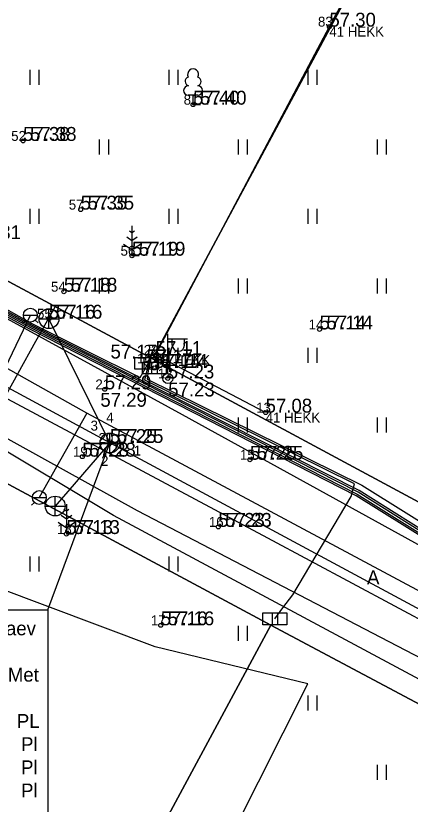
# Model space of a CAD drawing. Extents: x 640891 to 641083, y 6456526 to 6456669.
# Drawn here: x 640950.33 to 640970.21, y 6456556.9 to 6456596.6 of the extents above; entities that cross this region are included whole.
import ezdxf

# ---------------------------------------------------------------- set-up
doc = ezdxf.new("R2010")
doc.units = 0
for name, color, linetype in [('100koma2', 7, 'Continuous'), ('ABIJOONIS', 7, 'Continuous'), ('HALJASTUS', 7, 'Continuous'), ('KKAEV', 7, 'Continuous'), ('KORGUS', 7, 'Continuous'), ('KPKAABEL', 7, 'Continuous'), ('KTRASS', 7, 'Continuous'), ('MOOTKORG', 7, 'Continuous'), ('MOOTMPUNKT', 7, 'Continuous'), ('MOOTNR', 7, 'Continuous'), ('MOOTPIIR', 7, 'Continuous'), ('MPKAABEL', 7, 'Continuous'), ('PIIR', 7, 'Continuous'), ('POST', 7, 'Continuous'), ('PUU', 7, 'Continuous'), ('SITRASS', 7, 'Continuous'), ('SKTRASS', 7, 'Continuous'), ('TEE', 7, 'Continuous'), ('TORU_NR', 7, 'Continuous'), ('VKAEV', 7, 'Continuous'), ('VTRASS', 7, 'Continuous')]:
    doc.layers.add(name, color=color, linetype=linetype)

msp = doc.modelspace()

# ---------------------------------------------------------------- linework, layer by layer
at = {"layer": 'ABIJOONIS'}
msp.add_line((640951.949, 6456566.685), (640955.081, 6456575.091), dxfattribs=at)
msp.add_lwpolyline([(640942.489, 6456566.685), (640951.949, 6456566.685), (640951.949, 6456555.319), (640942.489, 6456555.319)], close=True, dxfattribs=at)
at = {"layer": 'HALJASTUS'}
for p, q in [((640951.045, 6456593.881), (640951.045, 6456593.119)), ((640951.5, 6456593.881), (640951.5, 6456593.119)), ((640958.045, 6456593.881), (640958.045, 6456593.119)), ((640958.5, 6456593.881), (640958.5, 6456593.119)), ((640965.045, 6456593.881), (640965.045, 6456593.119)), ((640965.5, 6456593.881), (640965.5, 6456593.119)), ((640954.545, 6456590.381), (640954.545, 6456589.619)), ((640955, 6456590.381), (640955, 6456589.619)), ((640961.545, 6456590.381), (640961.545, 6456589.619)), ((640962, 6456590.381), (640962, 6456589.619)), ((640968.545, 6456590.381), (640968.545, 6456589.619)), ((640969, 6456590.381), (640969, 6456589.619)), ((640951.045, 6456586.881), (640951.045, 6456586.119)), ((640951.5, 6456586.881), (640951.5, 6456586.119)), ((640958.045, 6456586.881), (640958.045, 6456586.119)), ((640958.5, 6456586.881), (640958.5, 6456586.119)), ((640965.045, 6456586.881), (640965.045, 6456586.119)), ((640965.5, 6456586.881), (640965.5, 6456586.119)), ((640954.545, 6456583.381), (640954.545, 6456582.619)), ((640955, 6456583.381), (640955, 6456582.619)), ((640961.545, 6456583.381), (640961.545, 6456582.619)), ((640962, 6456583.381), (640962, 6456582.619)), ((640968.545, 6456583.381), (640968.545, 6456582.619)), ((640969, 6456583.381), (640969, 6456582.619)), ((640958.045, 6456579.881), (640958.045, 6456579.119)), ((640958.5, 6456579.881), (640958.5, 6456579.119)), ((640965.045, 6456579.881), (640965.045, 6456579.119)), ((640965.5, 6456579.881), (640965.5, 6456579.119)), ((640961.545, 6456576.381), (640961.545, 6456575.619)), ((640962, 6456576.381), (640962, 6456575.619)), ((640968.545, 6456576.381), (640968.545, 6456575.619)), ((640969, 6456576.381), (640969, 6456575.619)), ((640951.045, 6456569.381), (640951.045, 6456568.619)), ((640951.5, 6456569.381), (640951.5, 6456568.619)), ((640958.045, 6456569.381), (640958.045, 6456568.619)), ((640958.5, 6456569.381), (640958.5, 6456568.619)), ((640961.545, 6456565.881), (640961.545, 6456565.119)), ((640962, 6456565.881), (640962, 6456565.119)), ((640965.045, 6456562.381), (640965.045, 6456561.619)), ((640965.5, 6456562.381), (640965.5, 6456561.619)), ((640968.545, 6456558.881), (640968.545, 6456558.119)), ((640969, 6456558.881), (640969, 6456558.119))]:
    msp.add_line(p, q, dxfattribs=at)
msp.add_lwpolyline([(640962.925, 6456576.62), (640957.383, 6456579.521), (640966.138, 6456596.056), (640972.417, 6456607.592), (640977.059, 6456616.501), (640985.041, 6456631.518)], dxfattribs=at)
at = {"layer": 'KKAEV'}
for p, q in [((640952.007, 6456580.849), (640952.007, 6456581.849)), ((640951.507, 6456581.349), (640952.507, 6456581.349)), ((640955.081, 6456574.591), (640955.081, 6456575.591)), ((640954.581, 6456575.091), (640955.581, 6456575.091)), ((640952.322, 6456571.413), (640952.322, 6456572.413)), ((640951.822, 6456571.913), (640952.822, 6456571.913))]:
    msp.add_line(p, q, dxfattribs=at)
for centre in [(640952.007, 6456581.349), (640955.081, 6456575.091), (640952.322, 6456571.913)]:
    msp.add_circle(centre, 0.5, dxfattribs=at)
at = {"layer": 'KORGUS'}
for centre in [(640959.27, 6456592.127), (640950.704, 6456590.303), (640953.606, 6456586.843), (640956.191, 6456584.52), (640952.76, 6456582.709), (640952.007, 6456581.349), (640965.643, 6456580.808), (640956.926, 6456579.098), (640957.317, 6456578.869), (640957.996, 6456578.338), (640954.822, 6456577.791), (640955.081, 6456575.091), (640953.689, 6456574.401), (640962.132, 6456574.246), (640960.539, 6456570.866), (640952.888, 6456570.505), (640957.641, 6456565.909)]:
    msp.add_circle(centre, 0.1, dxfattribs=at)
at = {"layer": 'KPKAABEL'}
msp.add_lwpolyline([(640977.507, 6456566.281), (640976.27, 6456566.95), (640967.49, 6456572.43), (640959.27, 6456576.625), (640951.05, 6456580.82), (640939.86, 6456586.9), (640935.075, 6456589.63), (640930.29, 6456592.36), (640924.23, 6456595.65), (640919.26, 6456598.135), (640914.117, 6456600.706)], dxfattribs=at)
at = {"layer": 'KTRASS'}
for points in [[(640955.081, 6456575.091), (640928.16, 6456589.63)], [(640955.081, 6456575.091), (640952.007, 6456581.349)], [(640955.081, 6456575.091), (640952.322, 6456571.913)], [(640976.059, 6456563.819), (640955.081, 6456575.091)]]:
    msp.add_lwpolyline(points, dxfattribs=at)
at = {"layer": 'MOOTMPUNKT'}
for centre in [(640966.138, 6456596.056), (640959.27, 6456592.127), (640950.704, 6456590.303), (640953.606, 6456586.843), (640956.191, 6456584.52), (640952.76, 6456582.709), (640952.007, 6456581.349), (640965.643, 6456580.808), (640957.383, 6456579.521), (640956.926, 6456579.098), (640957.317, 6456578.869), (640957.996, 6456578.338), (640954.822, 6456577.791), (640962.925, 6456576.62), (640955.081, 6456575.091), (640953.689, 6456574.401), (640962.132, 6456574.246), (640960.539, 6456570.866), (640952.888, 6456570.505), (640957.641, 6456565.909)]:
    msp.add_circle(centre, 0.1, dxfattribs=at)
at = {"layer": 'MOOTPIIR'}
msp.add_lwpolyline([(640976.662, 6456538.007), (640959.29, 6456546.142), (640961.328, 6456555.553), (640965.053, 6456562.959), (640957.364, 6456564.816), (640935.712, 6456572.952), (640933.007, 6456573.069), (640928.881, 6456566.092), (640925.582, 6456561.827), (640921.958, 6456562.765), (640911.417, 6456572.885), (640912.029, 6456574.013), (640921.076, 6456588.216), (640912.945, 6456593.7), (640910.627, 6456595.318), (640915.929, 6456603.505), (640924.706, 6456598.502), (640938.233, 6456631.58)], dxfattribs=at)
at = {"layer": 'MPKAABEL'}
for points in [[(640914.394, 6456601.133), (640919.49, 6456598.58), (640924.46, 6456596.09), (640927.495, 6456594.445), (640930.53, 6456592.8), (640935.32, 6456590.07), (640940.11, 6456587.34), (640945.625, 6456584.22), (640951.14, 6456581.1), (640953.87, 6456579.745), (640956.6, 6456578.39), (640957.06, 6456579.17)], [(640914.173, 6456600.793), (640919.31, 6456598.225), (640924.28, 6456595.74), (640927.31, 6456594.095), (640930.34, 6456592.45), (640935.125, 6456589.72), (640939.91, 6456586.99), (640945.495, 6456583.945), (640951.08, 6456580.9), (640959.31, 6456576.71), (640967.54, 6456572.52), (640971.93, 6456569.78), (640976.32, 6456567.04), (640977.56, 6456566.369)], [(640977.608, 6456566.451), (640976.37, 6456567.12), (640971.98, 6456569.865), (640967.59, 6456572.61), (640959.355, 6456576.785), (640951.12, 6456580.96), (640945.54, 6456584.015), (640939.96, 6456587.07), (640935.175, 6456589.8), (640930.39, 6456592.53), (640927.355, 6456594.18), (640924.32, 6456595.83), (640919.35, 6456598.315), (640914.227, 6456600.876)], [(640977.66, 6456566.54), (640976.42, 6456567.21), (640972.03, 6456569.95), (640967.64, 6456572.69), (640959.395, 6456576.855), (640951.15, 6456581.02), (640945.58, 6456584.09), (640940.01, 6456587.16), (640935.225, 6456589.89), (640930.44, 6456592.62), (640927.405, 6456594.27), (640924.37, 6456595.92), (640919.4, 6456598.405), (640914.283, 6456600.963)], [(640963.39, 6456566.23), (640963.8, 6456566.79), (640964.29, 6456567.45), (640967.23, 6456572.39), (640967.4, 6456573.03), (640956.84, 6456578.26), (640957.06, 6456579.17)], [(640957.06, 6456579.17), (640956.96, 6456578.31), (640962.37, 6456575.635), (640967.78, 6456572.96), (640976.57, 6456567.48), (640977.808, 6456566.792)]]:
    msp.add_lwpolyline(points, dxfattribs=at)
at = {"layer": 'PIIR'}
for points in [[(640957.22, 6456579.32), (640930.79, 6456593.51), (640960.76, 6456649.34), (640985.89, 6456632.73)], [(640983.63, 6456565.13), (640957.22, 6456579.32), (640985.89, 6456632.73), (641000.58, 6456623), (641011.01, 6456616.1)]]:
    msp.add_lwpolyline(points, close=True, dxfattribs=at)
for points in [[(640890.598, 6456615.08), (640904.36, 6456607.7), (640930.79, 6456593.51), (640957.22, 6456579.32), (640983.63, 6456565.13), (641002.905, 6456555.058)], [(640993.023, 6456550.09), (640989.66, 6456551.83), (640963.18, 6456565.91), (640936.74, 6456580.1), (640910.31, 6456594.28), (640890.598, 6456604.875)], [(640907.494, 6456525.865), (640936.74, 6456580.1), (640963.18, 6456565.91), (640941.583, 6456525.865)], [(640941.583, 6456525.865), (640963.18, 6456565.91), (640989.66, 6456551.83), (640975.643, 6456525.865)]]:
    msp.add_lwpolyline(points, dxfattribs=at)
at = {"layer": 'POST'}
for p, q in [((640957.996, 6456578.588), (640957.996, 6456580.588)), ((640957.996, 6456580.338), (640958.996, 6456580.338)), ((640958.223, 6456580.017), (640958.223, 6456580.338)), ((640958.836, 6456580.017), (640958.836, 6456580.338)), ((640956.79, 6456579.396), (640956.79, 6456578.799)), ((640957.062, 6456579.396), (640957.062, 6456578.799)), ((640957.181, 6456579.167), (640957.181, 6456578.571)), ((640957.453, 6456579.167), (640957.453, 6456578.571)), ((640957.996, 6456578.338), (640957.996, 6456578.338)), ((640963.254, 6456566.528), (640963.254, 6456565.932)), ((640963.526, 6456566.528), (640963.526, 6456565.932))]:
    msp.add_line(p, q, dxfattribs=at)
for points in [[(640956.329, 6456579.396), (640957.523, 6456579.396), (640957.523, 6456578.799), (640956.329, 6456578.799)], [(640956.72, 6456579.167), (640957.915, 6456579.167), (640957.915, 6456578.571), (640956.72, 6456578.571)], [(640962.793, 6456566.528), (640963.987, 6456566.528), (640963.987, 6456565.932), (640962.793, 6456565.932)]]:
    msp.add_lwpolyline(points, close=True, dxfattribs=at)
msp.add_circle((640957.996, 6456578.338), 0.25, dxfattribs=at)
msp.add_arc((640958.529, 6456580.017), 0.306, 180, 0, dxfattribs=at)
at = {"layer": 'PUU'}
for p, q in [((640959.51, 6456592.602), (640959.03, 6456592.602)), ((640959.27, 6456592.127), (640959.27, 6456592.602)), ((640959.65, 6456592.127), (640959.27, 6456592.127)), ((640956.191, 6456586.02), (640956.191, 6456584.52)), ((640956.191, 6456585.67), (640956.067, 6456585.753)), ((640956.316, 6456585.753), (640956.191, 6456585.67)), ((640955.767, 6456585.109), (640956.191, 6456584.826)), ((640956.191, 6456585.27), (640955.925, 6456585.447)), ((640956.458, 6456585.447), (640956.191, 6456585.27)), ((640956.191, 6456584.826), (640956.616, 6456585.109)), ((640956.551, 6456584.52), (640956.191, 6456584.52)), ((640952.888, 6456572.005), (640952.888, 6456570.505)), ((640952.888, 6456571.655), (640952.764, 6456571.738)), ((640953.012, 6456571.738), (640952.888, 6456571.655)), ((640952.888, 6456571.255), (640952.621, 6456571.433)), ((640953.155, 6456571.433), (640952.888, 6456571.255)), ((640952.464, 6456571.094), (640952.888, 6456570.811)), ((640952.888, 6456570.811), (640953.312, 6456571.094)), ((640953.248, 6456570.505), (640952.888, 6456570.505))]:
    msp.add_line(p, q, dxfattribs=at)
for centre, radius, start, end in [((640959.27, 6456593.647), 0.277, 332.5799, 207.4201), ((640959.1, 6456593.3), 0.233, 109.0217, 253.1415), ((640959.44, 6456593.3), 0.233, 286.8508, 70.9859), ((640959.032, 6456592.84), 0.238, 90.0016, 269.3953), ((640959.507, 6456592.84), 0.238, 270.6047, 89.9984)]:
    msp.add_arc(centre, radius, start, end, dxfattribs=at)
at = {"layer": 'SITRASS'}
for points in [[(640972.09, 6456562.42), (640955.26, 6456571.44), (640948.66, 6456575.39), (640939.25, 6456580.69), (640930.23, 6456585.64), (640921.93, 6456589.97), (640913.28, 6456594.36)], [(640948.66, 6456575.39), (640951.34, 6456580.22), (640952.32, 6456581.95)]]:
    msp.add_lwpolyline(points, dxfattribs=at)
at = {"layer": 'SKTRASS'}
msp.add_lwpolyline([(640975.84, 6456563.446), (640963.035, 6456570.289), (640950.405, 6456577.04), (640931.282, 6456587.261), (640918.683, 6456593.994), (640912.062, 6456597.533)], dxfattribs=at)
at = {"layer": 'TEE'}
for points in [[(640977.461, 6456566.201), (640971.27, 6456569.61), (640958.74, 6456576.51), (640944.02, 6456584.555), (640929.3, 6456592.6), (640917.98, 6456598.615), (640914.098, 6456600.678)], [(640911.131, 6456596.096), (640915.765, 6456593.725), (640927.19, 6456587.88), (640941.825, 6456579.785), (640956.46, 6456571.69), (640969.135, 6456565.09), (640975.008, 6456562.032)]]:
    msp.add_lwpolyline(points, dxfattribs=at)
at = {"layer": 'VKAEV'}
for p, q in [((640950.72, 6456581.53), (640951.42, 6456581.53)), ((640950.823, 6456581.283), (640950.683, 6456581.143)), ((640951.317, 6456581.283), (640951.457, 6456581.143)), ((640951.273, 6456572.093), (640951.133, 6456571.953)), ((640951.17, 6456572.34), (640951.87, 6456572.34)), ((640951.767, 6456572.093), (640951.907, 6456571.953))]:
    msp.add_line(p, q, dxfattribs=at)
for centre in [(640951.07, 6456581.53), (640951.52, 6456572.34)]:
    msp.add_circle(centre, 0.35, dxfattribs=at)
at = {"layer": 'VTRASS'}
for points in [[(640949.817, 6456578.894), (640951.07, 6456581.53)], [(640953.923, 6456576.584), (640949.817, 6456578.894)], [(640953.923, 6456576.584), (640951.52, 6456572.34)], [(640976.477, 6456564.528), (640953.923, 6456576.584)]]:
    msp.add_lwpolyline(points, dxfattribs=at)

# ---------------------------------------------------------------- texts
at = {"layer": '100koma2'}
for p in [(640966.138, 6456595.556), (640957.383, 6456579.021), (640962.925, 6456576.12)]:
    msp.add_text('41 HEKK', height=0.5, dxfattribs=at).set_placement(p)
at = {"layer": 'ABIJOONIS'}
for s, p in [('Kanalisatsioonikaev', (640943.077, 6456565.404)), ('Met', (640949.937, 6456563.071)), ('PL', (640950.392, 6456560.738)), ('Pl', (640950.602, 6456559.571)), ('Pl', (640950.602, 6456558.404)), ('Pl', (640950.602, 6456557.238))]:
    msp.add_text(s, height=0.7, dxfattribs=at).set_placement(p)
at = {"layer": 'KORGUS'}
for s, p in [('57.40', (640959.62, 6456592.127)), ('57.38', (640951.054, 6456590.303)), ('57.35', (640953.956, 6456586.843)), ('57.31', (640948.254, 6456585.354)), ('57.19', (640956.541, 6456584.52)), ('57.18', (640953.11, 6456582.709)), ('57.16', (640952.357, 6456581.349)), ('57.14', (640965.993, 6456580.808)), ('57.17', (640955.109, 6456579.343)), ('57.14', (640957.667, 6456578.869)), ('57.23', (640958.016, 6456577.433)), ('57.29', (640954.597, 6456576.914)), ('57.25', (640955.431, 6456575.091)), ('57.28', (640954.039, 6456574.401)), ('57.25', (640962.482, 6456574.246)), ('57.13', (640953.238, 6456570.505)), ('57.23', (640960.889, 6456570.866)), ('57.16', (640957.991, 6456565.909))]:
    msp.add_text(s, height=0.7, dxfattribs=at).set_placement(p)
at = {"layer": 'MOOTKORG'}
for s, p in [('57.30', (640966.138, 6456596.056)), ('57.40', (640959.27, 6456592.127)), ('57.38', (640950.704, 6456590.303)), ('57.35', (640953.606, 6456586.843)), ('57.19', (640956.191, 6456584.52)), ('57.18', (640952.76, 6456582.709)), ('57.16', (640952.007, 6456581.349)), ('57.14', (640965.643, 6456580.808)), ('57.11', (640957.383, 6456579.521)), ('57.17', (640956.926, 6456579.098)), ('57.14', (640957.317, 6456578.869)), ('57.23', (640957.996, 6456578.338)), ('57.29', (640954.822, 6456577.791)), ('57.08', (640962.925, 6456576.62)), ('57.25', (640955.081, 6456575.091)), ('57.28', (640953.689, 6456574.401)), ('57.25', (640962.132, 6456574.246)), ('57.13', (640952.888, 6456570.505)), ('57.23', (640960.539, 6456570.866)), ('57.16', (640957.641, 6456565.909))]:
    msp.add_text(s, height=0.7, dxfattribs=at).set_placement(p)
at = {"layer": 'MOOTNR'}
for s, p in [('83', (640965.563, 6456596.056)), ('81', (640958.795, 6456592.127)), ('52', (640950.104, 6456590.303)), ('57', (640953.006, 6456586.843)), ('56', (640955.616, 6456584.52)), ('54', (640952.11, 6456582.709)), ('55', (640951.407, 6456581.349)), ('14', (640965.093, 6456580.808)), ('22', (640956.783, 6456579.521)), ('10', (640956.451, 6456579.098)), ('11', (640956.942, 6456578.869)), ('12', (640957.496, 6456578.338)), ('21', (640954.347, 6456577.791)), ('13', (640962.45, 6456576.62)), ('20', (640954.506, 6456575.091)), ('19', (640953.214, 6456574.401)), ('15', (640961.632, 6456574.246)), ('16', (640960.064, 6456570.866)), ('18', (640952.413, 6456570.505)), ('17', (640957.141, 6456565.909))]:
    msp.add_text(s, height=0.5, dxfattribs=at).set_placement(p)
at = {"layer": 'TEE'}
msp.add_text('A', height=0.7, dxfattribs=at).set_placement((640968.035, 6456567.975))
at = {"layer": 'TORU_NR'}
for s, p in [('4', (640954.894, 6456576.12)), ('3', (640954.105, 6456575.715)), ('1', (640956.281, 6456574.459)), ('2', (640954.633, 6456573.937))]:
    msp.add_text(s, height=0.5, dxfattribs=at).set_placement(p)

doc.saveas('drawing.dxf')
